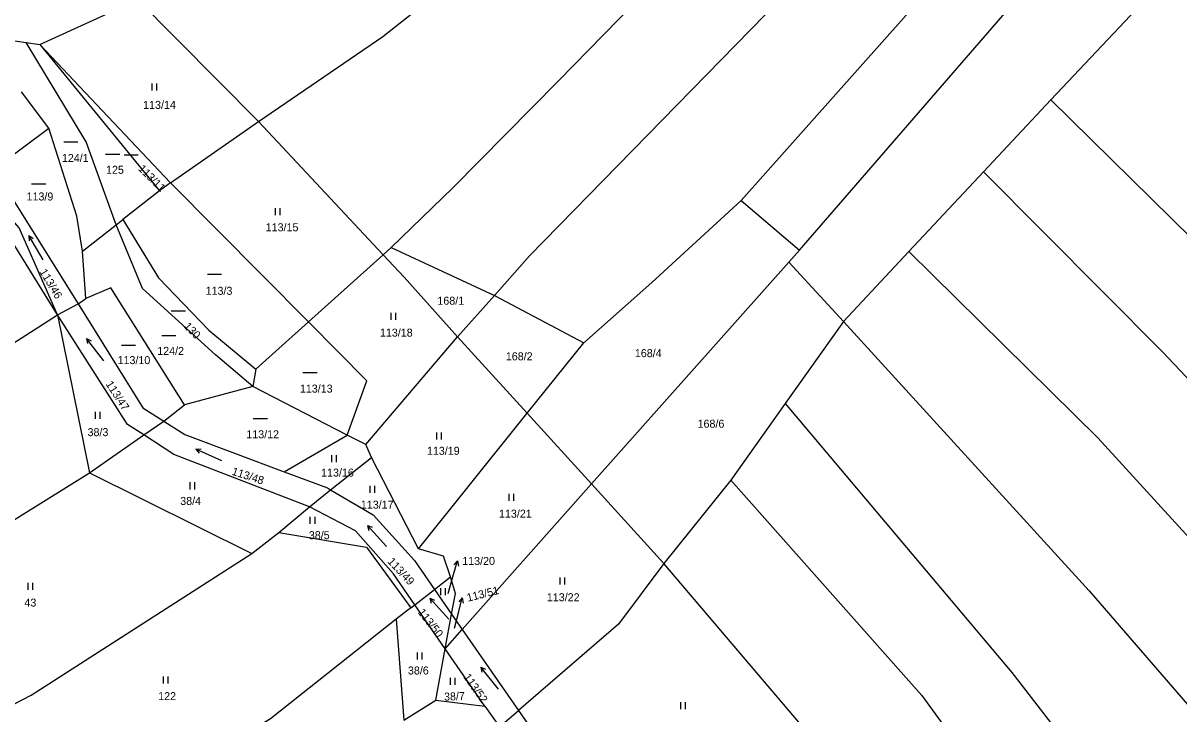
# Model space of a CAD drawing. Extents: x -7483133 to -743907, y -11317770 to -1129777.
# Drawn here: x -747616.9 to -747371.5, y -1131007.1 to -1130860.3 of the extents above; entities that cross this region are included whole.
import ezdxf

# ---------------------------------------------------------------- set-up
doc = ezdxf.new("R2010")
doc.units = 0
for name, color, linetype in [('Hranice parcel', 7, 'Continuous'), ('Parcelní čísla', 7, 'Continuous'), ('Pop  PČ popisy', 7, 'Continuous'), ('Značky kultur', 7, 'Continuous')]:
    doc.layers.add(name, color=color, linetype=linetype)

msp = doc.modelspace()

# ---------------------------------------------------------------- linework, layer by layer
at = {"layer": 'Hranice parcel'}
for p, q in [((-747370.72, -1130846.96), (-747398.68, -1130876.61)), ((-747566.95, -1130881.22), (-747592.89, -1130855.02)), ((-747620.11, -1130863.87), (-747616.32, -1130864.44)), ((-747616.32, -1130864.44), (-747613.42, -1130864.85)), ((-747585.62, -1130894.26), (-747613.42, -1130864.85)), ((-747613.42, -1130864.85), (-747587.99, -1130895.92)), ((-747611.5, -1130882.62), (-747617.27, -1130874.92)), ((-747412.97, -1130891.88), (-747398.68, -1130876.61)), ((-747585.62, -1130894.26), (-747566.95, -1130881.22)), ((-747540.5, -1130909.52), (-747566.95, -1130881.22)), ((-747624, -1130891.96), (-747611.5, -1130882.62)), ((-747428.85, -1130908.85), (-747412.97, -1130891.88)), ((-747587.99, -1130895.92), (-747595.75, -1130902.05)), ((-747585.62, -1130894.26), (-747587.99, -1130895.92)), ((-747556.37, -1130923.79), (-747585.62, -1130894.26)), ((-747464.43, -1130898), (-747452.04, -1130908.53)), ((-747604.33, -1130908.77), (-747597.18, -1130903.17)), ((-747597.18, -1130903.17), (-747595.75, -1130902.05)), ((-747538.78, -1130907.97), (-747540.5, -1130909.52)), ((-747538.78, -1130907.97), (-747516.82, -1130918.2)), ((-747603.65, -1130918.79), (-747604.33, -1130908.77)), ((-747556.37, -1130923.79), (-747540.5, -1130909.52)), ((-747452.04, -1130908.53), (-747454.36, -1130911.13)), ((-747442.73, -1130923.69), (-747428.85, -1130908.85)), ((-747496.26, -1130958.17), (-747454.36, -1130911.13)), ((-747454.36, -1130911.13), (-747442.73, -1130923.69)), ((-747609.63, -1130922.29), (-747605.27, -1130919.98)), ((-747605.27, -1130919.98), (-747603.65, -1130918.79)), ((-747524.7, -1130926.96), (-747516.82, -1130918.2)), ((-747516.82, -1130918.2), (-747497.88, -1130928.23)), ((-747609.63, -1130922.29), (-747602.88, -1130955.82)), ((-747567.53, -1130933.83), (-747556.37, -1130923.79)), ((-747442.73, -1130923.69), (-747455.08, -1130941.09)), ((-747544.17, -1130949.82), (-747524.7, -1130926.96)), ((-747509.89, -1130943.21), (-747524.7, -1130926.96)), ((-747509.89, -1130943.21), (-747497.88, -1130928.23)), ((-747567.53, -1130933.83), (-747568.14, -1130937.53)), ((-747568.14, -1130937.53), (-747582.67, -1130941.38)), ((-747548.12, -1130947.84), (-747568.14, -1130937.53)), ((-747587.06, -1130944.87), (-747582.67, -1130941.38)), ((-747455.08, -1130941.09), (-747466.65, -1130957.41)), ((-747591.34, -1130947.8), (-747587.06, -1130944.87)), ((-747533.01, -1130972.03), (-747509.89, -1130943.21)), ((-747496.26, -1130958.17), (-747509.89, -1130943.21)), ((-747602.88, -1130955.82), (-747591.34, -1130947.8)), ((-747561.51, -1130955.61), (-747548.12, -1130947.84)), ((-747544.17, -1130949.82), (-747548.12, -1130947.84)), ((-747542.97, -1130952.61), (-747544.17, -1130949.82)), ((-747551.66, -1130959.44), (-747542.97, -1130952.61)), ((-747533.01, -1130972.03), (-747542.97, -1130952.61)), ((-747670.43, -1130998.05), (-747602.88, -1130955.82)), ((-747602.88, -1130955.82), (-747568.39, -1130973)), ((-747466.65, -1130957.41), (-747480.85, -1130975.08)), ((-747556.12, -1130963.07), (-747551.66, -1130959.44)), ((-747523.68, -1130989.16), (-747496.26, -1130958.17)), ((-747480.85, -1130975.08), (-747496.26, -1130958.17)), ((-747562.63, -1130968.51), (-747556.12, -1130963.07)), ((-747568.39, -1130973), (-747562.63, -1130968.51)), ((-747445.77, -1131016.39), (-747480.85, -1130975.08)), ((-747529.57, -1130980.67), (-747526.17, -1130977.92)), ((-747533.76, -1130983.87), (-747529.57, -1130980.67)), ((-747529.57, -1130980.67), (-747525.94, -1130985.9)), ((-747534.58, -1130984.5), (-747533.76, -1130983.87)), ((-747527.29, -1130993.25), (-747533.76, -1130983.87)), ((-747534.58, -1130984.5), (-747537.72, -1130986.92)), ((-747527.29, -1130993.25), (-747525.94, -1130985.9)), ((-747525.94, -1130985.9), (-747523.68, -1130989.16)), ((-747537.72, -1130986.92), (-747536.11, -1131008.38)), ((-747527.29, -1130993.25), (-747523.68, -1130989.16)), ((-747523.68, -1130989.16), (-747511.77, -1131006.31)), ((-747529.3, -1131004.16), (-747527.29, -1130993.25)), ((-747518.9, -1131005.41), (-747527.29, -1130993.25)), ((-747536.11, -1131008.38), (-747529.3, -1131004.16)), ((-747529.3, -1131004.16), (-747518.9, -1131005.41)), ((-747518.9, -1131005.41), (-747515.79, -1131009.83)), ((-747515.79, -1131009.83), (-747511.77, -1131006.31)), ((-747511.77, -1131006.31), (-747505.21, -1131015.73))]:
    msp.add_line(p, q, dxfattribs=at)
for points in [[(-747566.95, -1130881.22), (-747540.53, -1130863.15), (-747518.65, -1130845.8), (-747451.1, -1130789.94), (-747421.34, -1130761.04), (-747390.31, -1130735.18)], [(-747375.64, -1130746.37), (-747442.58, -1130810.47), (-747503.21, -1130872.55), (-747525.65, -1130895.32), (-747538.78, -1130907.97)], [(-747516.82, -1130918.2), (-747509.43, -1130909.76), (-747453.02, -1130852.06), (-747406.54, -1130801.59), (-747362.47, -1130755.89)], [(-747464.43, -1130898), (-747419.65, -1130847.56), (-747377.79, -1130797.57), (-747349.46, -1130766.63)], [(-747452.04, -1130908.53), (-747389.53, -1130836.33), (-747337.16, -1130775.31)], [(-747613.42, -1130864.85), (-747598.03, -1130857.85), (-747592.89, -1130855.02)], [(-747597.18, -1130903.17), (-747603.54, -1130885.52), (-747616.32, -1130864.44)], [(-747398.68, -1130876.61), (-747368.77, -1130906.07), (-747355.31, -1130919.74), (-747329.82, -1130944.76), (-747315.8, -1130960.3), (-747283.94, -1130995.04), (-747236.86, -1131049.77), (-747149.88, -1131157.26)], [(-747604.33, -1130908.77), (-747605.55, -1130901.3), (-747611.5, -1130882.62)], [(-747624, -1130891.96), (-747619.89, -1130896.55), (-747605.27, -1130919.98)], [(-747177.21, -1131162.4), (-747204.46, -1131125.99), (-747254.48, -1131065.07), (-747271.84, -1131044.18), (-747315.73, -1130992.85), (-747375, -1130930.12), (-747412.97, -1130891.88)], [(-747609.63, -1130922.29), (-747623.92, -1130899.27), (-747627.71, -1130894.75)], [(-747609.63, -1130922.29), (-747617.8, -1130903.81), (-747626.52, -1130893.83)], [(-747497.88, -1130928.23), (-747483.39, -1130915.42), (-747464.43, -1130898)], [(-747568.14, -1130937.53), (-747576.11, -1130930.77), (-747591.59, -1130916.72), (-747597.18, -1130903.17)], [(-747595.75, -1130902.05), (-747588.22, -1130914.45), (-747577.5, -1130925.53), (-747567.53, -1130933.83)], [(-747524.7, -1130926.96), (-747536.03, -1130914.31), (-747540.5, -1130909.52)], [(-747428.85, -1130908.85), (-747388.68, -1130948.41), (-747322.17, -1131021.26), (-747287.68, -1131063.4), (-747257.57, -1131100.06), (-747233.11, -1131129.78), (-747216.94, -1131150.33), (-747204.99, -1131167.77)], [(-747582.67, -1130941.38), (-747598.35, -1130916.55), (-747603.65, -1130918.79)], [(-747605.27, -1130919.98), (-747591.5, -1130942.05), (-747587.06, -1130944.87)], [(-747696.99, -1130975.53), (-747672.66, -1130962.51), (-747641.8, -1130942.93), (-747609.63, -1130922.29)], [(-747591.34, -1130947.8), (-747594.77, -1130945.6), (-747609.63, -1130922.29)], [(-747548.12, -1130947.84), (-747543.96, -1130936.32), (-747556.37, -1130923.79)], [(-747442.73, -1130923.69), (-747390.58, -1130980.92), (-747354.26, -1131022.92), (-747339.61, -1131040.16), (-747322.4, -1131062.04), (-747305.83, -1131083.32), (-747294.44, -1131099.65), (-747274.04, -1131128.34), (-747243.06, -1131175.98)], [(-747455.08, -1130941.09), (-747407, -1130998.24), (-747346.3, -1131076.82), (-747308.86, -1131133.19), (-747276.68, -1131185.78)], [(-747587.06, -1130944.87), (-747582.62, -1130947.7), (-747561.51, -1130955.61)], [(-747556.12, -1130963.07), (-747584.92, -1130951.93), (-747591.34, -1130947.8)], [(-747561.51, -1130955.61), (-747552.29, -1130959.07), (-747551.66, -1130959.44)], [(-747466.65, -1130957.41), (-747426.05, -1131003.14), (-747390.52, -1131051.98), (-747379.77, -1131069.99), (-747357.62, -1131107.84), (-747342.16, -1131135.57), (-747326.23, -1131160.19), (-747318.42, -1131169.83), (-747304.55, -1131193.5)], [(-747551.66, -1130959.44), (-747542.61, -1130964.81), (-747533.86, -1130974.48), (-747529.57, -1130980.67)], [(-747533.76, -1130983.87), (-747538.28, -1130977.32), (-747546.35, -1130968.19), (-747556.12, -1130963.07)], [(-747562.63, -1130968.51), (-747544.05, -1130971.62), (-747534.58, -1130984.5)], [(-747526.17, -1130977.92), (-747527.69, -1130973.54), (-747533.01, -1130972.03)], [(-747647.48, -1131019.78), (-747615.24, -1131003.06), (-747568.39, -1130973)], [(-747480.85, -1130975.08), (-747490.53, -1130988), (-747511.77, -1131006.31)], [(-747525.94, -1130985.9), (-747525.13, -1130981.52), (-747526.17, -1130977.92)], [(-747537.72, -1130986.92), (-747564.39, -1131008.14), (-747611.03, -1131036.67), (-747627.11, -1131046.39)]]:
    msp.add_lwpolyline(points, dxfattribs=at)
at = {"layer": 'Pop  PČ popisy'}
for p, q in [((-747525.51, -1130977.47), (-747524.68, -1130974.58)), ((-747524.68, -1130974.58), (-747525.44, -1130975.41)), ((-747524.68, -1130974.58), (-747524.48, -1130975.69)), ((-747526.65, -1130981.51), (-747525.51, -1130977.47)), ((-747524.43, -1130985.33), (-747523.7, -1130982.42)), ((-747523.7, -1130982.42), (-747524.43, -1130983.27)), ((-747523.7, -1130982.42), (-747523.46, -1130983.51)), ((-747525.3, -1130988.86), (-747524.43, -1130985.33))]:
    msp.add_line(p, q, dxfattribs=at)
at = {"layer": 'Značky kultur'}
for p, q in [((-747589.56, -1130874.63), (-747589.56, -1130873.13)), ((-747588.56, -1130874.63), (-747588.56, -1130873.13)), ((-747608.3, -1130885.57), (-747605.3, -1130885.57)), ((-747599.42, -1130888.17), (-747596.42, -1130888.17)), ((-747595.5, -1130888.31), (-747592.5, -1130888.31)), ((-747615.13, -1130894.45), (-747612.13, -1130894.45)), ((-747563.38, -1130901.11), (-747563.38, -1130899.61)), ((-747562.38, -1130901.11), (-747562.38, -1130899.61)), ((-747612.71, -1130910.64), (-747615.71, -1130905.44)), ((-747615.71, -1130905.44), (-747615.66, -1130906.54)), ((-747615.71, -1130905.44), (-747614.79, -1130906.04)), ((-747577.79, -1130913.63), (-747574.79, -1130913.63)), ((-747585.47, -1130921.44), (-747582.47, -1130921.44)), ((-747538.76, -1130923.37), (-747538.76, -1130921.87)), ((-747537.76, -1130923.37), (-747537.76, -1130921.87)), ((-747599.81, -1130932.05), (-747603.5, -1130927.33)), ((-747603.5, -1130927.33), (-747603.29, -1130928.41)), ((-747603.5, -1130927.33), (-747602.5, -1130927.79)), ((-747587.5, -1130926.66), (-747584.5, -1130926.66)), ((-747596.08, -1130928.75), (-747593.08, -1130928.75)), ((-747557.53, -1130934.52), (-747554.53, -1130934.52)), ((-747601.56, -1130944.39), (-747601.56, -1130942.89)), ((-747600.56, -1130944.39), (-747600.56, -1130942.89)), ((-747568.07, -1130944.3), (-747565.07, -1130944.3)), ((-747529.1, -1130948.78), (-747529.1, -1130947.28)), ((-747528.1, -1130948.78), (-747528.1, -1130947.28)), ((-747580.24, -1130950.82), (-747579.15, -1130950.76)), ((-747574.76, -1130953.27), (-747580.24, -1130950.82)), ((-747580.24, -1130950.82), (-747579.55, -1130951.68)), ((-747551.41, -1130953.59), (-747551.41, -1130952.09)), ((-747550.41, -1130953.59), (-747550.41, -1130952.09)), ((-747581.47, -1130959.36), (-747581.47, -1130957.86)), ((-747580.47, -1130959.36), (-747580.47, -1130957.86)), ((-747543.24, -1130960.1), (-747543.24, -1130958.6)), ((-747542.24, -1130960.1), (-747542.24, -1130958.6)), ((-747513.74, -1130961.83), (-747513.74, -1130960.33)), ((-747512.74, -1130961.83), (-747512.74, -1130960.33)), ((-747555.95, -1130966.7), (-747555.95, -1130965.2)), ((-747554.95, -1130966.7), (-747554.95, -1130965.2)), ((-747539.8, -1130971.47), (-747543.81, -1130967.01)), ((-747543.81, -1130967.01), (-747543.53, -1130968.07)), ((-747543.81, -1130967.01), (-747542.79, -1130967.4)), ((-747615.89, -1130980.72), (-747615.89, -1130979.22)), ((-747614.89, -1130980.72), (-747614.89, -1130979.22)), ((-747502.9, -1130979.58), (-747502.9, -1130978.08)), ((-747501.9, -1130979.58), (-747501.9, -1130978.08)), ((-747528.22, -1130981.85), (-747528.22, -1130980.35)), ((-747527.22, -1130981.85), (-747527.22, -1130980.35)), ((-747526.57, -1130986.97), (-747530.58, -1130982.51)), ((-747530.58, -1130982.51), (-747530.3, -1130983.57)), ((-747530.58, -1130982.51), (-747529.56, -1130982.9)), ((-747533.17, -1130995.51), (-747533.17, -1130994.01)), ((-747532.17, -1130995.51), (-747532.17, -1130994.01)), ((-747587.12, -1131000.59), (-747587.12, -1130999.09)), ((-747586.12, -1131000.59), (-747586.12, -1130999.09)), ((-747516, -1131001.81), (-747519.77, -1130997.15)), ((-747519.77, -1130997.15), (-747519.55, -1130998.23)), ((-747519.77, -1130997.15), (-747518.77, -1130997.59)), ((-747526.2, -1131000.89), (-747526.2, -1130999.39)), ((-747525.2, -1131000.89), (-747525.2, -1130999.39)), ((-747477.3, -1131006.05), (-747477.3, -1131004.55)), ((-747476.3, -1131006.05), (-747476.3, -1131004.55))]:
    msp.add_line(p, q, dxfattribs=at)

# ---------------------------------------------------------------- texts
at = {"layer": 'Parcelní čísla'}
for s, p in [('113/14', (-747591.46, -1130878.54)), ('124/1', (-747608.71, -1130889.82)), ('125', (-747599.33, -1130892.33)), ('113/9', (-747616.22, -1130898)), ('113/15', (-747565.43, -1130904.54)), ('113/3', (-747578.19, -1130918.03)), ('168/1', (-747528.97, -1130920.14)), ('113/18', (-747541.17, -1130926.92)), ('124/2', (-747588.46, -1130930.8)), ('168/2', (-747514.43, -1130931.95)), ('168/4', (-747487.03, -1130931.28)), ('113/10', (-747596.89, -1130932.76)), ('113/13', (-747558.17, -1130938.81)), ('168/6', (-747473.71, -1130946.27)), ('38/3', (-747603.26, -1130948.06)), ('113/12', (-747569.54, -1130948.52)), ('113/19', (-747531.19, -1130952.02)), ('113/16', (-747553.66, -1130956.65)), ('38/4', (-747583.58, -1130962.67)), ('113/17', (-747545.22, -1130963.46)), ('113/21', (-747515.88, -1130965.38)), ('38/5', (-747556.27, -1130969.95)), ('113/20', (-747523.69, -1130975.43)), ('113/22', (-747505.72, -1130983.13)), ('43', (-747616.67, -1130984.27)), ('38/6', (-747535.22, -1130998.69)), ('122', (-747588.26, -1131004.14))]:
    msp.add_text(s, height=1.7, dxfattribs=at).set_placement(p)
for s, rotation, p in [('113/11', 315, (-747592.63, -1130891.39)), ('113/46', 301, (-747613.54, -1130913.13)), ('130', 314, (-747582.94, -1130924.84)), ('113/47', 303, (-747599.48, -1130936.99)), ('113/48', 342, (-747572.75, -1130956.22)), ('113/49', 313, (-747539.66, -1130974.8)), ('113/51', 14, (-747522.5, -1130983.24)), ('113/50', 308, (-747533.21, -1130985.52)), ('113/52', 305, (-747523.52, -1130999.23)), ('38/7', 2, (-747527.53, -1131004.26))]:
    msp.add_text(s, height=1.7, rotation=rotation, dxfattribs=at).set_placement(p)

doc.saveas('drawing.dxf')
